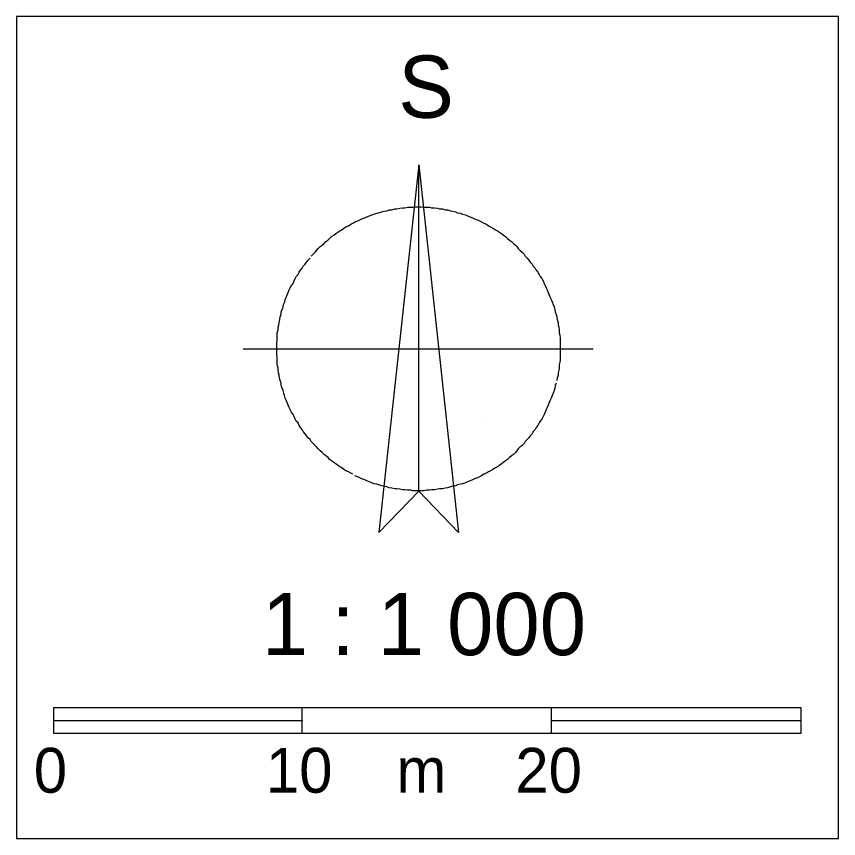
# Model space of a CAD drawing. Extents: x -597749 to -595427, y -1168718 to -1166900.
# Drawn here: x -596500.37 to -596467.37, y -1168118.64 to -1168085.64 of the extents above; entities that cross this region are included whole.
import ezdxf

# ---------------------------------------------------------------- set-up
doc = ezdxf.new("R2010")
doc.units = 0
for name, color, linetype in [('BUDOVY', 7, 'Continuous'), ('ramraz', 7, 'Continuous'), ('Vrstva 1', 7, 'Continuous'), ('Vrstva 24', 7, 'Continuous')]:
    doc.layers.add(name, color=color, linetype=linetype)

# ---------------------------------------------------------------- blocks, each defined once
blk = doc.blocks.new('POINT_DISPLAY')
blk.add_line((0, 0), (0, 0))

msp = doc.modelspace()

# ---------------------------------------------------------------- linework, layer by layer
at = {"layer": 'ramraz'}
msp.add_lwpolyline([(-596500.37, -1168118.643), (-596467.37, -1168118.643), (-596467.37, -1168085.643), (-596500.37, -1168085.643)], close=True, dxfattribs=at)
at = {"layer": 'Vrstva 1'}
msp.add_line((-596491.263, -1168098.982), (-596477.224, -1168098.982), dxfattribs=at)
for points in [[(-596484.223, -1168104.702), (-596484.223, -1168091.602), (-596485.823, -1168106.362), (-596484.223, -1168104.702)], [(-596484.223, -1168104.702), (-596484.223, -1168091.602), (-596482.623, -1168106.362), (-596484.223, -1168104.702)], [(-596488.544, -1168095.262), (-596488.463, -1168095.182), (-596488.383, -1168095.102), (-596488.324, -1168095.042), (-596488.263, -1168094.962), (-596488.184, -1168094.882), (-596488.104, -1168094.822), (-596488.024, -1168094.762), (-596487.944, -1168094.682), (-596487.864, -1168094.622), (-596487.803, -1168094.562), (-596487.723, -1168094.482), (-596487.624, -1168094.422), (-596487.544, -1168094.362), (-596487.464, -1168094.302), (-596487.384, -1168094.242), (-596487.303, -1168094.202), (-596487.223, -1168094.142), (-596487.143, -1168094.082), (-596487.043, -1168094.042), (-596486.944, -1168093.982), (-596486.863, -1168093.942), (-596486.783, -1168093.882), (-596486.663, -1168093.842), (-596486.584, -1168093.802), (-596486.503, -1168093.762), (-596486.384, -1168093.722), (-596486.304, -1168093.682), (-596486.204, -1168093.642), (-596486.104, -1168093.602), (-596486.023, -1168093.582), (-596485.903, -1168093.542), (-596485.823, -1168093.522), (-596485.703, -1168093.482), (-596485.604, -1168093.462), (-596485.504, -1168093.442), (-596485.403, -1168093.402), (-596485.304, -1168093.402), (-596485.183, -1168093.362), (-596485.103, -1168093.362), (-596484.984, -1168093.342), (-596484.863, -1168093.322), (-596484.783, -1168093.322), (-596484.664, -1168093.302), (-596484.544, -1168093.302), (-596484.464, -1168093.302), (-596484.343, -1168093.282), (-596484.223, -1168093.282), (-596484.223, -1168093.282)], [(-596484.223, -1168093.282), (-596484.123, -1168093.282), (-596484.023, -1168093.302), (-596483.903, -1168093.302), (-596483.784, -1168093.302), (-596483.703, -1168093.322), (-596483.583, -1168093.322), (-596483.463, -1168093.342), (-596483.383, -1168093.362), (-596483.263, -1168093.362), (-596483.163, -1168093.402), (-596483.064, -1168093.402), (-596482.943, -1168093.442), (-596482.863, -1168093.462), (-596482.743, -1168093.482), (-596482.664, -1168093.522), (-596482.543, -1168093.542), (-596482.464, -1168093.582), (-596482.344, -1168093.602), (-596482.263, -1168093.642), (-596482.163, -1168093.682), (-596482.063, -1168093.722), (-596481.984, -1168093.762), (-596481.863, -1168093.802), (-596481.784, -1168093.842), (-596481.703, -1168093.882), (-596481.603, -1168093.942), (-596481.503, -1168093.982), (-596481.423, -1168094.042), (-596481.344, -1168094.082), (-596481.244, -1168094.142), (-596481.143, -1168094.202), (-596481.063, -1168094.242), (-596480.983, -1168094.302), (-596480.903, -1168094.362), (-596480.824, -1168094.422), (-596480.744, -1168094.482), (-596480.664, -1168094.562), (-596480.583, -1168094.622), (-596480.503, -1168094.682), (-596480.423, -1168094.762), (-596480.343, -1168094.822), (-596480.283, -1168094.882), (-596480.224, -1168094.962), (-596480.144, -1168095.042), (-596480.064, -1168095.102), (-596479.984, -1168095.182), (-596479.944, -1168095.262), (-596479.864, -1168095.342), (-596479.803, -1168095.422), (-596479.743, -1168095.502), (-596479.663, -1168095.582), (-596479.623, -1168095.662), (-596479.543, -1168095.742), (-596479.503, -1168095.822), (-596479.443, -1168095.902), (-596479.384, -1168096.002), (-596479.344, -1168096.082), (-596479.283, -1168096.162), (-596479.223, -1168096.262), (-596479.184, -1168096.362), (-596479.144, -1168096.442), (-596479.103, -1168096.542), (-596479.063, -1168096.622), (-596479.024, -1168096.722), (-596478.983, -1168096.822), (-596478.943, -1168096.922), (-596478.903, -1168097.002), (-596478.864, -1168097.102), (-596478.823, -1168097.202), (-596478.784, -1168097.302), (-596478.763, -1168097.402), (-596478.743, -1168097.502), (-596478.704, -1168097.602), (-596478.684, -1168097.702), (-596478.664, -1168097.802), (-596478.623, -1168097.922), (-596478.624, -1168098.022), (-596478.604, -1168098.122), (-596478.583, -1168098.222), (-596478.583, -1168098.342), (-596478.563, -1168098.442), (-596478.544, -1168098.542), (-596478.544, -1168098.662), (-596478.543, -1168098.762), (-596478.544, -1168098.882), (-596478.543, -1168098.982), (-596478.543, -1168098.982), (-596478.544, -1168099.082), (-596478.543, -1168099.202), (-596478.544, -1168099.302), (-596478.543, -1168099.422), (-596478.563, -1168099.522), (-596478.583, -1168099.622), (-596478.583, -1168099.742), (-596478.604, -1168099.842), (-596478.624, -1168099.942), (-596478.623, -1168100.042), (-596478.663, -1168100.162), (-596478.683, -1168100.262)], [(-596486.863, -1168104.022), (-596486.944, -1168103.982), (-596487.043, -1168103.922), (-596487.143, -1168103.882), (-596487.224, -1168103.822), (-596487.304, -1168103.762), (-596487.383, -1168103.722), (-596487.464, -1168103.662), (-596487.544, -1168103.602), (-596487.623, -1168103.542), (-596487.724, -1168103.482), (-596487.803, -1168103.422), (-596487.863, -1168103.342), (-596487.944, -1168103.282), (-596488.024, -1168103.222), (-596488.104, -1168103.142), (-596488.183, -1168103.082), (-596488.263, -1168103.002), (-596488.323, -1168102.922), (-596488.383, -1168102.862), (-596488.463, -1168102.782), (-596488.543, -1168102.702), (-596488.583, -1168102.622), (-596488.663, -1168102.562), (-596488.724, -1168102.482), (-596488.783, -1168102.402), (-596488.864, -1168102.302), (-596488.904, -1168102.222), (-596488.963, -1168102.142), (-596489.023, -1168102.062), (-596489.063, -1168101.962), (-596489.143, -1168101.882), (-596489.183, -1168101.802), (-596489.224, -1168101.702), (-596489.263, -1168101.622), (-596489.324, -1168101.522), (-596489.384, -1168101.422), (-596489.424, -1168101.342), (-596489.463, -1168101.242), (-596489.504, -1168101.142), (-596489.544, -1168101.042), (-596489.583, -1168100.962), (-596489.604, -1168100.862), (-596489.643, -1168100.762), (-596489.663, -1168100.662), (-596489.704, -1168100.562), (-596489.744, -1168100.462), (-596489.743, -1168100.362), (-596489.784, -1168100.262), (-596489.804, -1168100.162), (-596489.824, -1168100.042), (-596489.844, -1168099.942), (-596489.864, -1168099.842), (-596489.863, -1168099.742), (-596489.904, -1168099.622), (-596489.903, -1168099.522), (-596489.903, -1168099.422), (-596489.903, -1168099.302), (-596489.923, -1168099.202), (-596489.924, -1168099.082), (-596489.923, -1168098.982), (-596489.923, -1168098.982), (-596489.924, -1168098.882), (-596489.923, -1168098.762), (-596489.903, -1168098.662), (-596489.903, -1168098.542), (-596489.903, -1168098.442), (-596489.904, -1168098.342), (-596489.864, -1168098.222), (-596489.863, -1168098.122), (-596489.843, -1168098.022), (-596489.824, -1168097.922), (-596489.803, -1168097.802), (-596489.783, -1168097.702), (-596489.743, -1168097.602), (-596489.744, -1168097.502), (-596489.703, -1168097.402), (-596489.664, -1168097.302), (-596489.644, -1168097.202), (-596489.603, -1168097.102), (-596489.583, -1168097.002), (-596489.543, -1168096.922), (-596489.504, -1168096.822), (-596489.463, -1168096.722), (-596489.424, -1168096.622), (-596489.384, -1168096.542), (-596489.324, -1168096.442), (-596489.264, -1168096.362), (-596489.223, -1168096.262), (-596489.184, -1168096.162), (-596489.144, -1168096.082), (-596489.064, -1168096.002), (-596489.023, -1168095.902), (-596488.963, -1168095.822), (-596488.904, -1168095.742), (-596488.864, -1168095.662), (-596488.783, -1168095.582), (-596488.724, -1168095.502), (-596488.664, -1168095.422), (-596488.584, -1168095.342)], [(-596478.704, -1168100.362), (-596478.743, -1168100.462), (-596478.763, -1168100.562), (-596478.783, -1168100.662), (-596478.824, -1168100.762), (-596478.863, -1168100.862), (-596478.904, -1168100.962), (-596478.944, -1168101.042), (-596478.983, -1168101.142), (-596479.024, -1168101.242), (-596479.063, -1168101.342), (-596479.103, -1168101.422), (-596479.144, -1168101.522), (-596479.183, -1168101.622), (-596479.223, -1168101.702), (-596479.283, -1168101.802), (-596479.343, -1168101.882), (-596479.383, -1168101.962), (-596479.443, -1168102.062), (-596479.503, -1168102.142), (-596479.543, -1168102.222), (-596479.623, -1168102.302), (-596479.664, -1168102.402), (-596479.743, -1168102.482), (-596479.804, -1168102.562), (-596479.863, -1168102.622), (-596479.943, -1168102.702), (-596479.984, -1168102.782), (-596480.064, -1168102.862), (-596480.144, -1168102.922), (-596480.224, -1168103.002), (-596480.284, -1168103.082), (-596480.343, -1168103.142), (-596480.423, -1168103.222), (-596480.503, -1168103.282), (-596480.583, -1168103.342), (-596480.663, -1168103.422), (-596480.743, -1168103.482), (-596480.823, -1168103.542), (-596480.903, -1168103.602), (-596480.983, -1168103.662), (-596481.064, -1168103.722), (-596481.144, -1168103.762), (-596481.243, -1168103.822), (-596481.343, -1168103.882), (-596481.423, -1168103.922), (-596481.503, -1168103.982), (-596481.603, -1168104.022), (-596481.704, -1168104.082), (-596481.783, -1168104.122), (-596481.863, -1168104.162), (-596481.984, -1168104.202), (-596482.063, -1168104.242), (-596482.163, -1168104.282), (-596482.264, -1168104.322), (-596482.343, -1168104.362), (-596482.463, -1168104.402), (-596482.543, -1168104.422), (-596482.664, -1168104.442), (-596482.743, -1168104.482), (-596482.864, -1168104.502), (-596482.943, -1168104.522), (-596483.064, -1168104.562), (-596483.164, -1168104.582), (-596483.264, -1168104.602), (-596483.384, -1168104.602), (-596483.463, -1168104.622), (-596483.584, -1168104.642), (-596483.704, -1168104.642), (-596483.783, -1168104.662), (-596483.903, -1168104.662), (-596484.024, -1168104.682), (-596484.123, -1168104.682), (-596484.224, -1168104.682), (-596484.224, -1168104.682), (-596484.344, -1168104.682), (-596484.463, -1168104.682), (-596484.544, -1168104.662), (-596484.664, -1168104.662), (-596484.784, -1168104.642), (-596484.864, -1168104.642), (-596484.984, -1168104.622), (-596485.104, -1168104.602), (-596485.184, -1168104.602), (-596485.303, -1168104.582), (-596485.404, -1168104.562), (-596485.504, -1168104.522), (-596485.603, -1168104.502), (-596485.703, -1168104.482), (-596485.823, -1168104.442), (-596485.904, -1168104.422), (-596486.024, -1168104.402), (-596486.103, -1168104.362), (-596486.203, -1168104.322), (-596486.303, -1168104.282), (-596486.384, -1168104.242), (-596486.503, -1168104.202), (-596486.584, -1168104.162), (-596486.663, -1168104.122), (-596486.784, -1168104.082)]]:
    msp.add_lwpolyline(points, dxfattribs=at)
for points in [[(-596484.223, -1168104.702), (-596484.223, -1168091.602), (-596485.823, -1168106.362), (-596484.223, -1168104.702)], [(-596484.223, -1168104.702), (-596484.223, -1168091.602), (-596482.623, -1168106.362), (-596484.223, -1168104.702)]]:
    msp.add_lwpolyline(points, close=True, dxfattribs=at)
at = {"layer": 'Vrstva 24'}
for p, q in [((-596488.905, -1168114.414), (-596488.905, -1168113.402)), ((-596478.89, -1168114.414), (-596478.889, -1168113.401)), ((-596498.884, -1168113.908), (-596488.869, -1168113.908)), ((-596478.889, -1168113.908), (-596468.874, -1168113.908))]:
    msp.add_line(p, q, dxfattribs=at)
msp.add_lwpolyline([(-596498.883, -1168114.414), (-596468.874, -1168114.414), (-596468.874, -1168113.401), (-596498.884, -1168113.402), (-596498.883, -1168114.414)], dxfattribs=at)

# ---------------------------------------------------------------- block references
at = {"layer": 'BUDOVY'}
msp.add_blockref('POINT_DISPLAY', (-596481.682, -1168101.835), dxfattribs=at)

# ---------------------------------------------------------------- texts
at = {"layer": 'Vrstva 1'}
for s, height, p in [('S', 2.5, (-596485.043, -1168089.712)), ('1 : 1 000', 2.5, (-596490.517, -1168111.281)), ('0', 1.8, (-596499.674, -1168116.802)), ('10', 1.8, (-596490.361, -1168116.802)), ('20', 1.8, (-596480.346, -1168116.802)), ('m', 1.8, (-596485.118, -1168116.802))]:
    msp.add_text(s, height=height, dxfattribs=at).set_placement(p)

doc.saveas('drawing.dxf')
